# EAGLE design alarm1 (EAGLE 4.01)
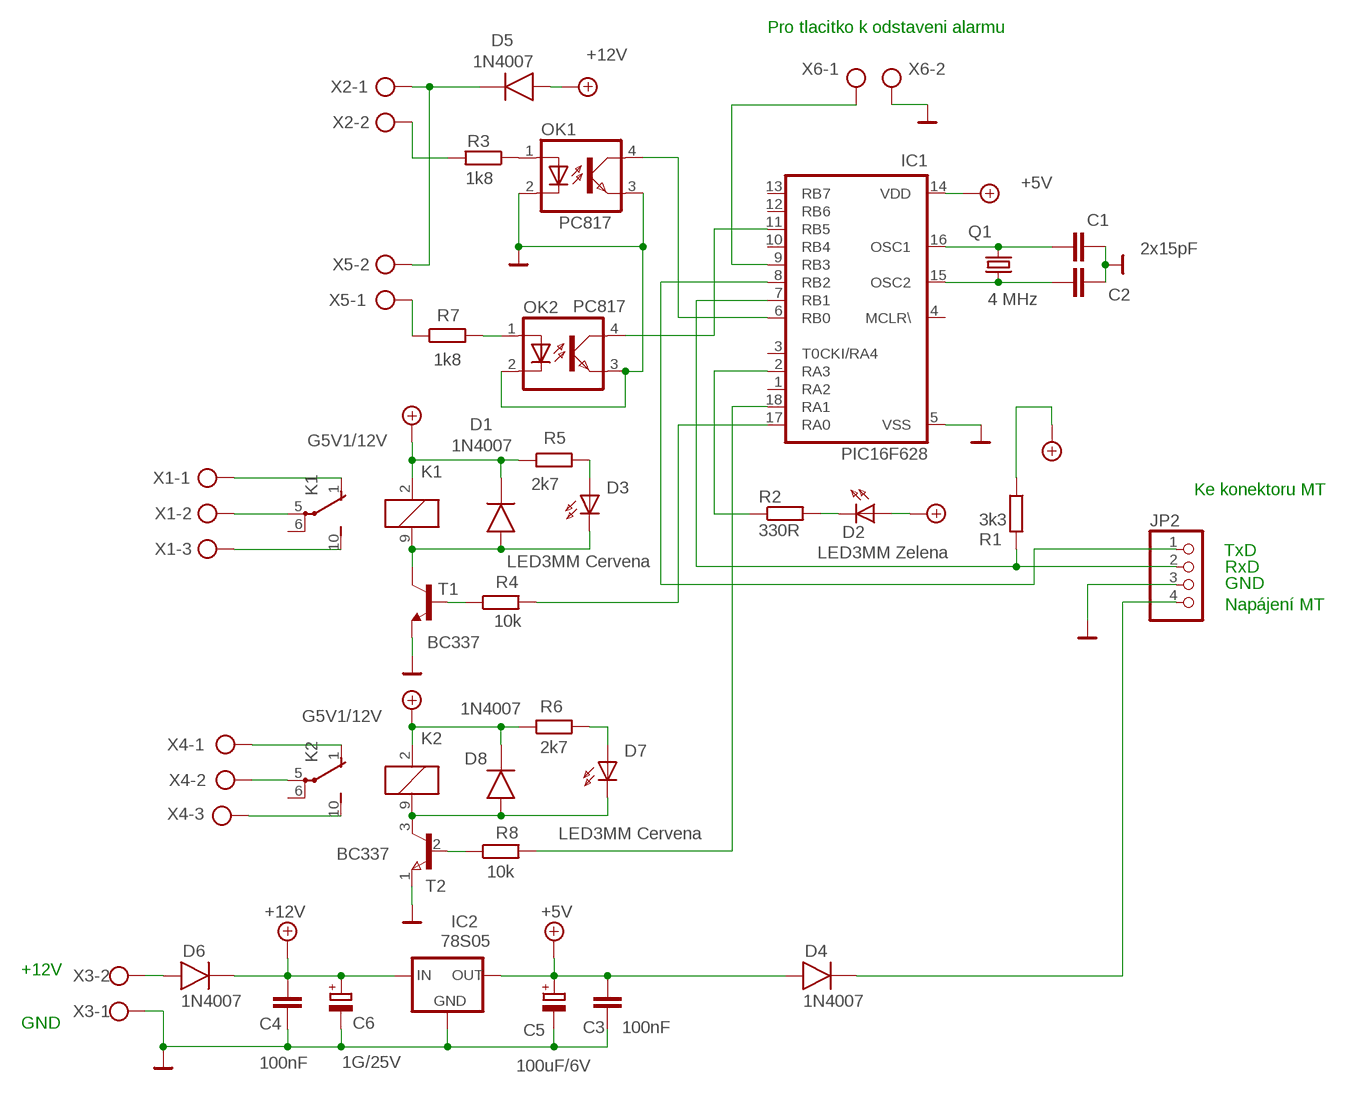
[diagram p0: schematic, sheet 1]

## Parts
C1  2x15pF  C-EU025-025X050  [C025-025X050]
C2  C-EU025-025X050  [C025-025X050]
C3  100nF  C-EU025-025X050  [C025-025X050]
C4  100nF  C-EU025-025X050  [C025-025X050]
C5  100uF/6V  CPOL-EUE2.5-7  [E2,5-7]
C6  1G/25V  CPOL-EUE5-13  [E5-13]
D1  1N4007  [DO41]
D2  LED3MM Zelena  LED3MM  [LED3MM]
D3  LED3MM Cervena  LED3MM  [LED3MM]
D4  1N4007  [DO41]
D5  1N4007  [DO41]
D6  1N4007  [DO41]
D7  LED3MM Cervena  LED3MM  [LED3MM]
D8  1N4007  [DO41]
IC1  PIC16F628  PIC16F84AP  [DIL18]
IC2  78S05  78XXS  [78XXS]
JP2  PINHD-1X4  [1X04]
K1  G5V1/12V  G5V1  [G5V1]
K2  G5V1/12V  G5V1  [G5V1]
OK1  PC817  [DIL04]
OK2  PC817  [DIL04]
Q1  4 MHz  HC49U-V  [HC49U-V]
R1  3k3  R-EU_0207/10  [0207/10]
R2  330R  R-EU_0207/10  [0207/10]
R3  1k8  R-EU_0207/10  [0207/10]
R4  10k  R-EU_0207/10  [0207/10]
R5  2k7  R-EU_0207/10  [0207/10]
R6  2k7  R-EU_0207/10  [0207/10]
R7  1k8  R-EU_0207/10  [0207/10]
R8  10k  R-EU_0207/10  [0207/10]
T1  BC337  [TO92]
T2  BC337  BC337-40  [TO-92C]
X1  AK500/3  [AK500/3]
X2  AK500/2  [AK500/2]
X3  AK500/2  [AK500/2]
X4  AK500/3  [AK500/3]
X5  AK500/2  [AK500/2]
X6  AK500/2  [AK500/2]

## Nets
0V: C1.1 C2.1 C3.1 C4.1 C5.- C6.- IC1.5(VSS) IC2.GND JP2.3 OK1.2(C) OK1.3(EMIT) OK2.2(C) OK2.3(EMIT) T1.1(E) T2.1(E) X3.1 X6.2
+5V: C3.2 C5.+ D2.A D4.A IC1.14(VDD) IC2.OUT R1.1
+12V: C4.2 C6.+ D1.K D5.A D6.K D8.K IC2.IN K1.2 K2.2 R5.1 R6.1
N$1: C1.2 IC1.16(OSC1) Q1.2
N$2: C2.2 IC1.15(OSC2) Q1.1
N$3: R3.2 X2.2
N$4: OK1.1(A) R3.1
N$5: IC1.9(RB3) X6.1
N$6: K1.5(2:P) X1.2
N$7: K1.1(2:O) X1.1
N$8: IC1.17(RA0) R4.2
N$9: IC1.6(RB0) OK1.4(COL)
N$10: K2.5(2:P) X4.2
N$11: IC1.11(RB5) OK2.4(COL)
N$12: OK2.1(A) R7.2
N$13: D7.K(C) D8.A K2.9 T2.3(C)
N$14: D6.A X3.2
N$15: K2.1(2:O) X4.1
N$16: K1.10(2:S) X1.3
N$17: IC1.2(RA3) R2.1
N$18: D2.K(C) R2.2
N$19: D1.A D3.K(C) K1.9 T1.3(C)
N$20: D4.K JP2.4
N$22: D7.A R6.2
N$23: D3.A R5.2
N$24: D5.K X2.1 X5.2
N$25: R4.1 T1.2(B)
N$26: IC1.7(RB1) JP2.2 R1.2
N$27: IC1.8(RB2) JP2.1
N$29: K2.10(2:S) X4.3
N$30: R8.1 T2.2(B)
N$31: IC1.18(RA1) R8.2
N$32: R7.1 X5.1
Unconnected: IC1.1(RA2) IC1.3(T0CKI/RA4) IC1.4(MCLR\) IC1.10(RB4) IC1.12(RB6) IC1.13(RB7) K1.6(2:P) K2.6(2:P)

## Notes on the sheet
- Pro tlacitko k odstaveni alarmu
- Ke konektoru MT
- TxD
- RxD
- GND
- Napájení MT
- +12V
- GND

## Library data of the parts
C1-C4 = rcl:C-EU: CAPACITOR, European symbol
C5 C6 = rcl:CPOL-EU: POLARIZED CAPACITOR, European symbol
D1 D4-D6 D8 = GM99:1N4007
D2 D3 D7 = led:LED3MM: LED
IC1 = microchip:PIC16F8*: MICROCONTROLLER 8-Bit PIC16F8X Family - CMOS Flash/EEPROM Pin Compatible : PIC16F83, PIC16CR83, PIC16F84A, PIC16CR84 see also PIC16C*
IC2 = v-reg:78XXS: VOLTAGE REGULATOR
JP2 = pinhead:PINHD-1X4: PIN HEADER
K1 K2 = relay:G5V1: RELAY 1 x switch, 0.5 A/125 V AC, 1 A/24 V DC , Omron
OK1 OK2 = optocoupler:PC817: SHARP OPTO COUPLER
Q1 = crystal:HC49U-V: CRYSTAL
R1-R8 = rcl:R-EU_: RESISTOR, European symbol
T1 = transistor-npn:BC337: NPN TRANSISTOR
T2 = GM99:BC337-40
X1 X4 = con-ptr500:AK500/3: CONNECTOR
X2 X3 X5 X6 = con-ptr500:AK500/2: CONNECTOR

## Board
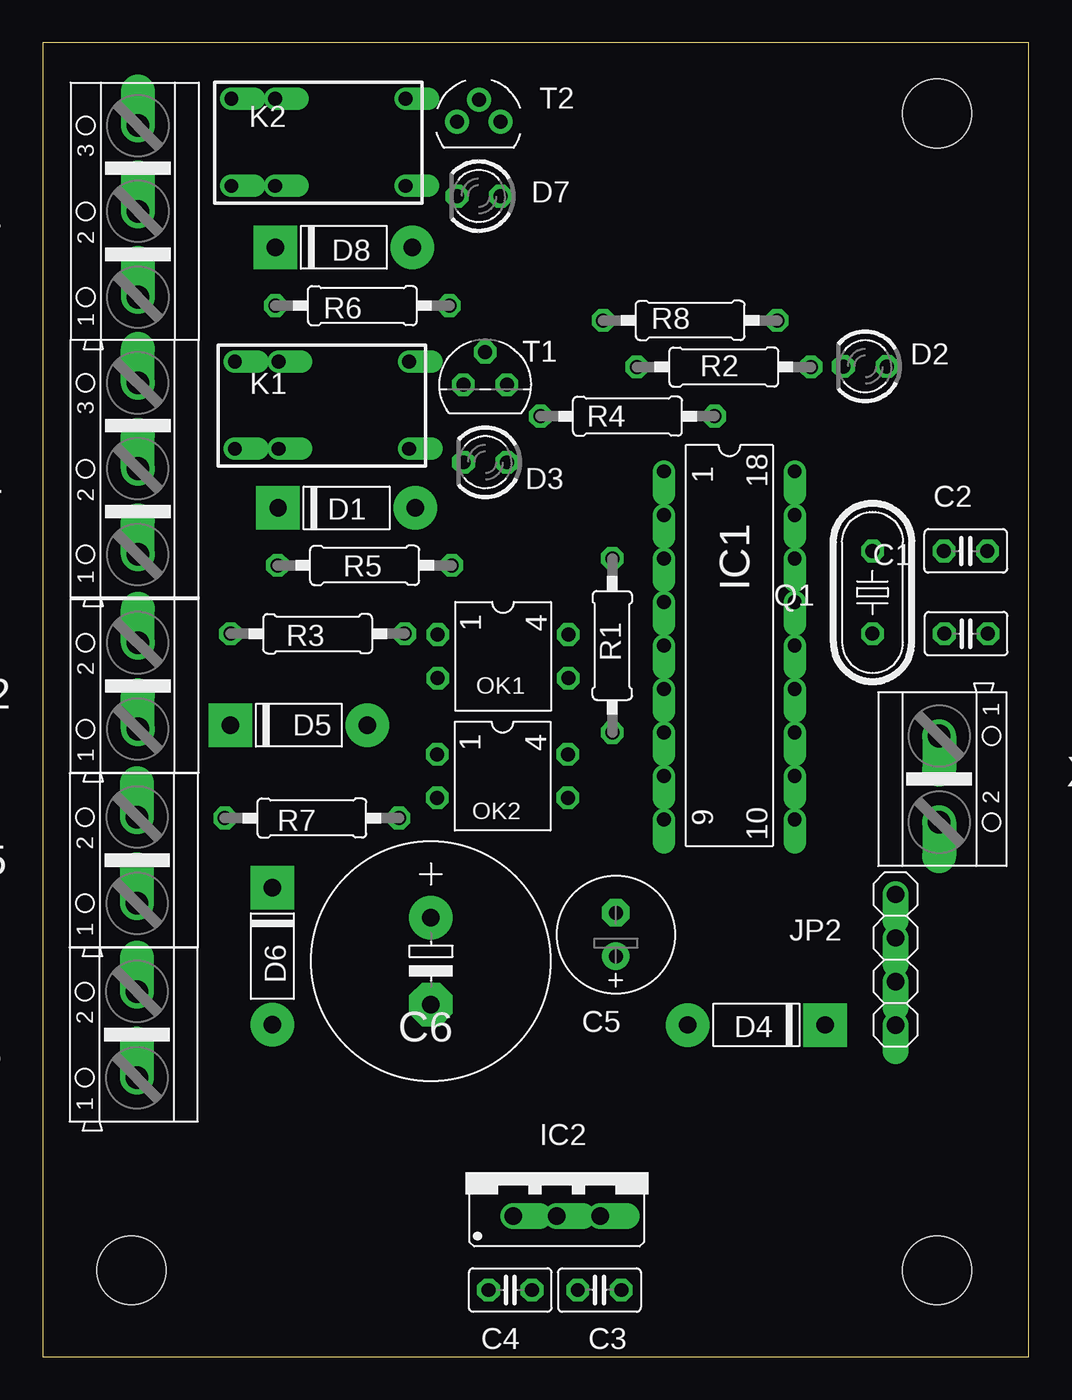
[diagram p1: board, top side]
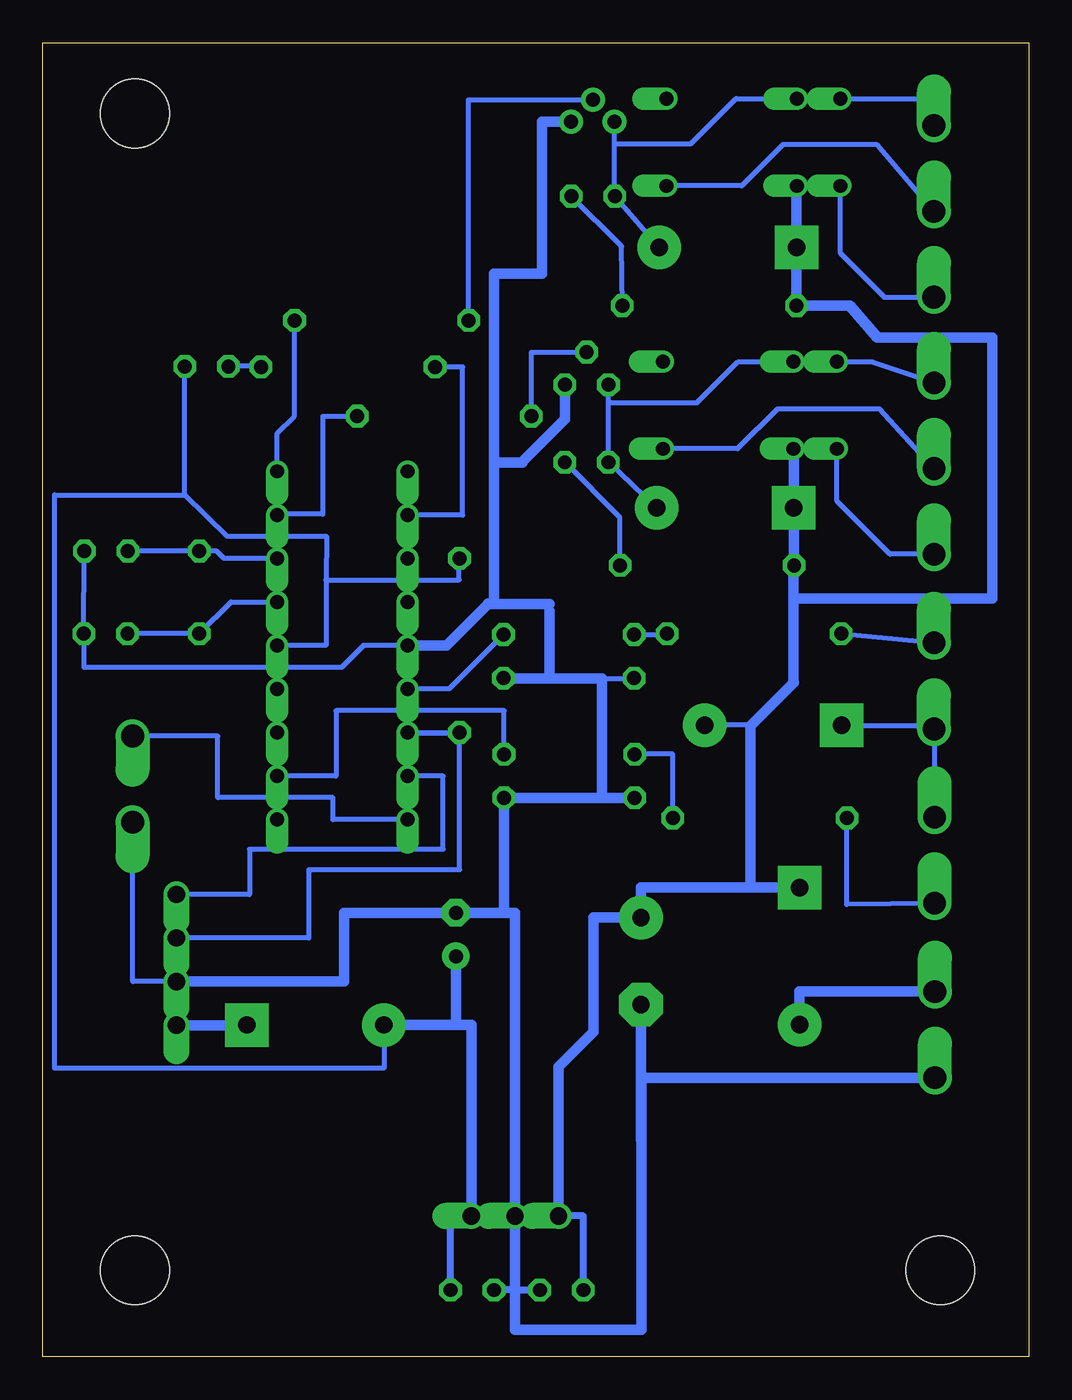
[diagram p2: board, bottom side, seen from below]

Size 57.54 x 76.66 mm. Coordinates in mm from the lower left corner, seen from the top.
Outline: 0,0 57.54,0 57.54,76.66 0,76.66 0,0
Copper layers used: Bottom
Holes 4 mm at 52.17,72.54 5.17,5.04 52.17,5.04

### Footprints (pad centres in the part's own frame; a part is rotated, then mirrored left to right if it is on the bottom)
C025-025X050 = drill 0.813 octagon: 1 -1.27,0; 2 1.27,0
E2,5-7 = drill 0.813 pad 1.6 round: + -1.27,0 | drill 0.813 pad 1.6 octagon: - 1.27,0
E5-13 = drill 1.016 pad 2.54 round: + -2.54,0 | drill 1.016 pad 2.54 octagon: - 2.54,0
DO41 = drill 1.016 pad 2.54 round: A 8,0 | drill 1.016 pad 2.54 square: K 0,0
LED3MM = drill 0.813 octagon: A -1.27,0; K 1.27,0
DIL18 = drill 0.813 offset: 1 -10.16,-3.81; 2 -7.62,-3.81; 3 -5.08,-3.81; 4 -2.54,-3.81; 5 0,-3.81; 6 2.54,-3.81; 7 5.08,-3.81; 8 7.62,-3.81; 9 10.16,-3.81; 10 10.16,3.81; 11 7.62,3.81; 12 5.08,3.81; 13 2.54,3.81; 14 0,3.81; 15 -2.54,3.81; 16 -5.08,3.81; 17 -7.62,3.81; 18 -10.16,3.81
78XXS = drill 1.016 offset: GND 0,-2.54; IN -2.54,-2.54; OUT 2.54,-2.54
1X04 = drill 1.016 offset: 1 -3.81,0; 2 -1.27,0; 3 1.27,0; 4 3.81,0
G5V1 = drill 0.813 offset: 1 -5.08,-2.54; 2 -2.54,-2.54; 5 5.08,-2.54; 6 5.08,2.54; 9 -2.54,2.54; 10 -5.08,2.54
DIL04 = drill 0.813 octagon: 1 -1.27,-3.81; 2 1.27,-3.81; 3 1.27,3.81; 4 -1.27,3.81
HC49U-V = drill 0.813 octagon: 1 -2.413,0; 2 2.413,0
0207/10 = drill 0.813 octagon: 1 -5.08,0; 2 5.08,0
TO92 = drill 0.813 octagon: 1 1.27,0; 2 0,1.905; 3 -1.27,0
TO-92C = drill 0.813 pad 1.397 round: 1 0,0; 2 1.27,1.27; 3 0,2.54
AK500/3 = drill 1.321 offset: 1 -5.004,0; 2 0,0; 3 5.004,0
AK500/2 = drill 1.321 offset: 1 -2.515,0; 2 2.515,0

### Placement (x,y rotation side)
C1  53.85,47.01 180 top
C2  53.88,42.18 180 top
C3  32.48,3.89 0 top
C4  27.27,3.89 180 top
C5  33.44,24.63 90 top
C6  22.64,23.08 270 top
D1  13.73,49.52 0 top
D2  47.98,57.78 180 top
D3  25.82,52.18 180 top
D4  45.64,19.36 180 top
D5  10.93,36.85 0 top
D6  13.39,27.37 270 top
D7  25.44,67.71 180 top
D8  13.57,64.73 0 top
IC1  40.06,41.5 270 top
IC2  29.99,10.75 0 top
JP2  49.75,23.16 270 top
K1  16.29,55.51 0 top
K2  16.08,70.85 0 top
OK1  26.85,40.86 270 top
OK2  26.82,33.88 270 top
Q1  48.42,44.59 90 top
R1  33.23,41.5 270 top
R2  39.74,57.75 0 top
R3  16.04,42.18 180 top
R4  34.12,54.87 0 top
R5  18.78,46.17 0 top
R6  18.65,61.32 0 top
R7  15.7,31.43 0 top
R8  37.77,60.46 0 top
T1  25.81,56.7 0 top
T2  26.72,72.06 90 top
X1  5.54,51.81 90 top
X2  5.54,39.14 90 top
X3  5.49,18.79 90 top
X4  5.55,66.83 90 top
X5  5.5,28.97 90 top
X6  52.3,33.7 270 top

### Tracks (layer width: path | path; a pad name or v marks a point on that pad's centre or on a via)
0V
  Bottom 0.305: OK1.2 23.03,39.57 24.91,39.57 27.99,39.57 | 29.56,52.17 29.56,52.22 | 30.65,39.57 OK1.3 | C2.1 C1.1 | C2.1 | 27.99,43.51 27.99,43.92 | OK2.3 24.91,32.61 OK2.2 27.93,32.61 | IC1.5 38.83,41.5 40.1,40.22 55.14,40.22 55.14,42.18 C2.1 | C5.- | C5.- | C5.- 30.63,25.9 | JP2.3 52.29,21.88 X6.2
  Bottom 0.406: C4.1 29.99,3.89 C3.1
  Bottom 0.61: 30.65,39.57 24.91,39.57 24.91,32.61 | 27.99,39.57 27.99,43.51 | T2.1 28.42,72.06 28.42,63.2 31.21,63.2 31.21,52.17 | T1.1 27.08,54.7 29.56,52.22 | 31.21,52.17 29.56,52.17 | IC1.5 33.99,41.5 31.57,43.92 | 27.99,43.92 31.57,43.92 | 22.63,12.38 22.63,1.56 29.99,1.56 29.99,3.92 | JP2.3 39.97,21.89 39.97,25.9 C5.- | 30.63,25.9 OK2.3 | 22.63,12.66 22.63,12.69 | C6.- 22.64,12.66 22.63,12.66 | 22.63,12.38 22.63,12.66 | X3.1 22.63,16.27 22.63,12.38 | 29.99,3.92 29.99,3.89 | OK2.2 29.99,32.61 | 29.99,3.92 29.99,3.94 | 29.99,3.94 29.99,3.95 | 29.99,3.94 IC2.GND | IC2.GND | C5.- 29.99,25.9 IC2.GND | 31.57,43.92 31.57,43.93 31.21,43.93 31.21,52.17
+5V
  Bottom 0.305: IC1.14 41.02,41.5 41.02,45.3 | R1.1 33.24,46.58 33.24,45.32 41.02,45.32 41.02,45.3 | 49.25,50.29 D2.A | 49.25,50.29 46.78,47.87 40.99,47.87 41.02,45.3 | D4.A 37.64,16.83 56.85,16.83 56.85,50.28 49.25,50.28 | 49.25,50.28 | 49.25,50.28 49.25,50.29
  Bottom 0.406: IC2.OUT 33.75,8.21 C3.2
  Bottom 0.61: D4.A 32.53,19.36 32.53,19.37 | IC2.OUT 32.53,19.37 | C5.+ 33.44,19.37 32.53,19.37
+12V
  Bottom 0.305: D8.K | 13.56,68.29 K2.2 | R6.1 13.57,61.34 13.58,61.34 | R5.1 13.73,46.18 13.74,46.18 | K1.2 13.73,52.96 | D5.A 16.25,36.85 16.25,36.81 | 2.15,45.01 2.15,44.45 | 13.73,39.33 13.74,39.33 | D6.K 16.25,27.37
  Bottom 0.406: IC2.IN 26,8.21 C4.2 | C6.+
  Bottom 0.61: D8.K 13.56,68.29 | 13.57,61.34 D8.K | 13.73,46.18 D1.K 13.73,52.96 | 13.73,39.33 16.25,36.81 16.25,27.37 | R6.1 10.44,61.32 8.83,59.46 2.15,59.46 2.15,45.01 2.15,44.22 13.74,44.22 | 13.74,44.22 13.74,46.18 | 13.74,39.33 13.74,44.22 | D6.K 22.65,27.37 C6.+ | IC2.IN 27.45,16.9 25.42,18.94 25.42,25.62 C6.+
N$1
  Bottom 0.305: IC1.16 46.98,46.58 47.39,46.99 48.38,46.99 Q1.2 C1.2 | C1.2 | C1.2 52.57,46.99
N$2
  Bottom 0.305: IC1.15 46.56,44.04 Q1.1 52.62,42.18 | 52.62,42.18 C2.2 | 52.62,42.18 52.62,42.19
N$3
  Bottom 0.305: R3.2 10.97,42.17 X2.2
N$4
  Bottom 0.305: OK1.1 23.04,42.11 21.12,42.11 R3.1
N$5
  Bottom 0.305: IC1.9 40.61,31.34 40.61,32.63 47.34,32.63 47.34,36.21 X6.1
N$6
  Bottom 0.305: K1.5 17,52.97 14.68,55.3 8.71,55.3 5.51,51.75 X1.2
N$7
  Bottom 0.305: K1.1 11.21,49.92 8.11,46.83 5.53,46.83 | 5.53,46.83 5.48,46.83 | X1.1 5.53,46.83
N$8
  Bottom 0.305: R4.2 41.19,54.88 41.19,49.15 43.86,49.15 43.86,49.12 IC1.17
N$9
  Bottom 0.305: OK1.4 30.65,42.11 30.68,42.11 33.83,38.97 36.24,38.97 IC1.6
N$10
  Bottom 0.305: K2.5 16.75,68.31 14.35,70.72 8.88,70.72 5.58,66.84 X4.2
N$11
  Bottom 0.305: IC1.11 40.43,33.88 40.43,37.7 30.63,37.7 OK2.4
N$12
  Bottom 0.305: OK2.1 20.78,35.16 R7.2
N$13
  Bottom 0.305: 24.18,70.77 T2.3 | D7.K 24.18,67.69 24.18,70.77 | D7.K | 24.18,70.77 19.73,70.77 17.09,73.41 13.53,73.41 13.54,73.4 K2.9 | D8.A D7.K
N$14
  Bottom 0.406: 13.41,19.37 D6.A
  Bottom 0.61: X3.2 13.41,21.3 13.41,19.37
N$15
  Bottom 0.305: K2.1 11,64.37 8.44,61.81 5.54,61.81 | 5.53,61.81 5.54,61.81 | 5.54,61.81 X4.1
N$16
  Bottom 0.305: K1.10 11.22,58.04 | K1.10 | K1.10 9.11,58.04 5.53,56.83 X1.3
N$17
  Bottom 0.305: R2.1 33.04,57.75 33.04,49.1 36.22,49.1 | 36.22,49.1 36.22,49.12 IC1.2 | 36.22,49.1 36.22,49.07
N$18
  Bottom 0.305: D2.K 44.82,57.79 R2.2
N$19
  Bottom 0.305: K1.9 16.98,58.05 19.37,55.65 24.35,55.65 | T1.3 24.54,55.65 24.35,55.65 | 24.35,55.65 24.55,55.65 D3.K 21.74,49.51 D1.A
N$20
  Bottom 0.61: JP2.4 | JP2.4 | D4.K 45.64,19.34 JP2.4
N$22
  Bottom 0.305: D7.A 26.72,67.72 | D7.A | R6.2 23.78,64.78 D7.A
N$23
  Bottom 0.305: R5.2 23.87,46.15 | R5.2 | D3.A 23.87,48.97 R5.2
N$24
  Bottom 0.305: 5.51,36.81 X2.1 | X5.2 5.5,36.8 5.51,36.81 | 5.51,36.81 5.51,36.79 10.88,36.79 D5.K
N$25
  Bottom 0.305: T1.2 | T1.2 | R4.1 29.04,58.6 T1.2
N$26
  Bottom 0.305: 36.25,36.4 IC1.7 | R1.2 33.23,36.4 36.25,36.4 | 36.25,36.4 33.22,36.4 33.22,28.41 42.03,28.41 42.03,24.42 JP2.2 | JP2.2 | JP2.2
N$27
  Bottom 0.305: IC1.8 34.18,33.88 34.18,29.6 45.49,29.6 45.49,26.96 JP2.1 | JP2.1 | JP2.1
N$29
  Bottom 0.305: 5.58,71.82 5.58,71.83 | 5.58,71.83 X4.3 | K2.10 5.58,73.39 5.58,71.83
N$30
  Bottom 0.305: 32.71,60.46 32.71,60.45 | R8.1 32.71,60.46 | T2.2 32.71,73.33 32.71,60.46
N$31
  Bottom 0.305: R8.2 42.85,54.88 43.86,53.88 43.86,51.69 43.84,51.67 43.84,51.66 IC1.18
N$32
  Bottom 0.305: 10.64,31.43 10.64,31.45 | 10.64,31.43 R7.1 | X5.1 10.64,26.38 10.64,31.43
